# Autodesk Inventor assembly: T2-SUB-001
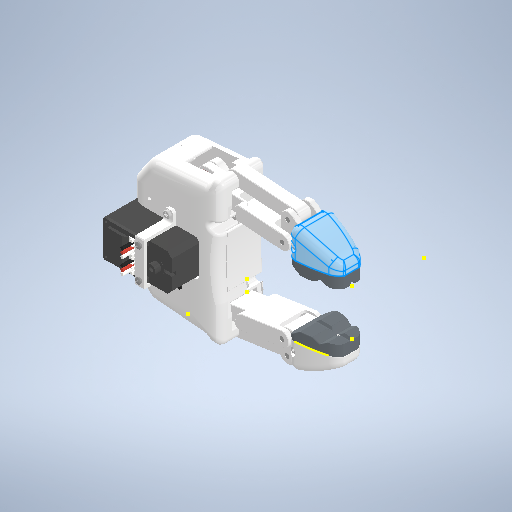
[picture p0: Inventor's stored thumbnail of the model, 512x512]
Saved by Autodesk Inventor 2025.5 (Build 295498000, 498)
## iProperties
Created: 2026-10
Part Number: T2-SUB-001
Document SubType Name: Assembly
Designer: Luis MuÃ±oz
Project: TESIS 2 - Plataforma mecatrÃ³nica preventiva desacoplada
Description: Gripper adaptativo instrumentado con puntas flexibles
Author: Luis M
Title: Gripper adaptativo instrumentado con puntas flexibles
Revision Number: 00
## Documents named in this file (22)
- C:\Users\Luis M\Desktop\TESIS\CAD_TESIS_ORGANIZADO\01_ENSAMBLES\GRIPPER_ADAPTATIVO_INSTRUMENTADO.iam
- C:\Users\Luis M\Desktop\TESIS\CAD_TESIS_ORGANIZADO\02_PIEZAS\GRIPPER\PLACA_INFERIOR_GRIPPER.ipt
- C:\Users\Luis M\Desktop\TESIS\CAD_TESIS_ORGANIZADO\02_PIEZAS\GRIPPER\ESLABON_INTERIOR.ipt
- C:\Users\Luis M\Desktop\TESIS\CAD_TESIS_ORGANIZADO\02_PIEZAS\GRIPPER\ESLABON_EXTERIOR.ipt
- C:\Users\Luis M\Desktop\TESIS\CAD_TESIS_ORGANIZADO\02_PIEZAS\GRIPPER\ESLABON_DISTAL.ipt
- C:\Users\Luis M\Desktop\TESIS\CAD_TESIS_ORGANIZADO\02_PIEZAS\GRIPPER\CARCASA_DISTAL_DEDO.ipt
- C:\Users\Luis M\Desktop\TESIS\CAD_TESIS_ORGANIZADO\02_PIEZAS\GRIPPER\SOPORTE_PUNTA_FLEXIBLE.ipt
- C:\Users\Luis M\Desktop\TESIS\CAD_TESIS_ORGANIZADO\02_PIEZAS\GRIPPER\PUNTA_CONTACTO_REMOVIBLE.ipt
- C:\Users\Luis M\Desktop\TESIS\CAD_TESIS_ORGANIZADO\02_PIEZAS\GRIPPER\PLACA_SUPERIOR_GRIPPER.ipt
- C:\Users\Luis M\Desktop\TESIS\CAD_TESIS_ORGANIZADO\02_PIEZAS\COMERCIALES_COMPARTIDAS\FEETECH_ST-3215-C018.iam
- C:\Users\Luis M\Desktop\TESIS\CAD_TESIS_ORGANIZADO\02_PIEZAS\GRIPPER\ACOPLE_EJE_SERVOMOTOR.ipt
- C:\Users\Luis M\Desktop\TESIS\CAD_TESIS_ORGANIZADO\02_PIEZAS\GRIPPER\LEVA_ACCIONAMIENTO.ipt
- C:\Users\Luis M\Desktop\TESIS\CAD_TESIS_ORGANIZADO\02_PIEZAS\GRIPPER\BIELA_MOTRIZ.ipt
- C:\Users\Luis M\Desktop\TESIS\CAD_TESIS_ORGANIZADO\02_PIEZAS\COMERCIALES_COMPARTIDAS\MCM_99461A931_TORNILLO_M2_5X8.ipt
- C:\Users\Luis M\Desktop\TESIS\CAD_TESIS_ORGANIZADO\02_PIEZAS\COMERCIALES_COMPARTIDAS\INSERTO_ROSCADO_M3_D5_L5.ipt
- C:\Users\Luis M\Desktop\TESIS\CAD_TESIS_ORGANIZADO\02_PIEZAS\COMERCIALES_COMPARTIDAS\PASADOR_CILINDRICO_D3X16.ipt
- C:\Users\Luis M\Desktop\TESIS\CAD_TESIS_ORGANIZADO\02_PIEZAS\COMERCIALES_COMPARTIDAS\PASADOR_CILINDRICO_D3X24.ipt
- C:\Users\Luis M\Desktop\TESIS\CAD_TESIS_ORGANIZADO\02_PIEZAS\COMERCIALES_COMPARTIDAS\COJINETE_LISO_D3_D6_L5.ipt
- C:\Users\Luis M\Desktop\TESIS\CAD_TESIS_ORGANIZADO\02_PIEZAS\COMERCIALES_COMPARTIDAS\TORNILLO_HEX_INTERIOR_M3X10.ipt
- C:\Users\Luis M\Desktop\TESIS\CAD_TESIS_ORGANIZADO\02_PIEZAS\GRIPPER\BRIDA_SERVOMOTOR.ipt
- C:\Users\Luis M\Desktop\TESIS\CAD_TESIS_ORGANIZADO\02_PIEZAS\COMERCIALES_COMPARTIDAS\TORNILLO_M2X4.ipt
- C:\Users\Luis M\Desktop\TESIS\CAD_TESIS_ORGANIZADO\02_PIEZAS\COMERCIALES_COMPARTIDAS\TORNILLO_HEX_INTERIOR_M3X6.ipt
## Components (70 placed, 21 different names)
1. PLACA_INFERIOR_GRIPPER:1
2. ESLABON_INTERIOR:1 — Coincidencia:1, Coincidencia:2, Coincidencia:12, Coincidencia:13, Coincidencia:49, Nivelación:13, Coincidencia:65, Coincidencia:66, Nivelación:15, Coincidencia:87, Coincidencia:92
3. ESLABON_INTERIOR:2 — Coincidencia:3, Coincidencia:4, Coincidencia:9, Coincidencia:14, Coincidencia:47, Nivelación:10, Coincidencia:63, Coincidencia:64, Nivelación:14, Coincidencia:89
4. ESLABON_EXTERIOR:1 — Coincidencia:6, Coincidencia:7, Coincidencia:11, Coincidencia:69
5. ESLABON_EXTERIOR:2 — Coincidencia:5, Coincidencia:8, Coincidencia:10, Coincidencia:70
6. ESLABON_DISTAL:1
7. ESLABON_DISTAL:2
8. Distal_Shell:2 — Coincidencia:15, Coincidencia:23, Nivelación:2, Nivelación:3, Coincidencia:71, Coincidencia:73, Coincidencia:74, Coincidencia:136
9. Distal_Shell:3 — Coincidencia:16, Coincidencia:24, Nivelación:1, Nivelación:4, Coincidencia:77, Coincidencia:78, Coincidencia:137
10. SOPORTE_PUNTA_FLEXIBLE:1 — Nivelación:3, Coincidencia:28, Coincidencia:136
11. SOPORTE_PUNTA_FLEXIBLE:2 — Coincidencia:29, Nivelación:4, Coincidencia:137
12. PUNTA_CONTACTO_REMOVIBLE:1 — Coincidencia:17, Coincidencia:18, Coincidencia:22, Coincidencia:23, Nivelación:2, Coincidencia:28, Coincidencia:57, Coincidencia:58, Coincidencia:59, Coincidencia:60, Coincidencia:61, Coincidencia:62, Coincidencia:72
13. PUNTA_CONTACTO_REMOVIBLE:2 — Coincidencia:19, Coincidencia:20, Coincidencia:21, Coincidencia:24, Nivelación:1, Coincidencia:29, Coincidencia:51, Coincidencia:52, Coincidencia:53, Coincidencia:54, Coincidencia:55, Coincidencia:56, Coincidencia:75, Coincidencia:76
14. PLACA_SUPERIOR_GRIPPER:1 — Coincidencia:25, Coincidencia:26, Coincidencia:27, Coincidencia:30, Coincidencia:31, Nivelación:5, Coincidencia:98, Coincidencia:99, Coincidencia:100, Coincidencia:102, Coincidencia:103, Coincidencia:104, Coincidencia:105, Coincidencia:106, Coincidencia:122, Coincidencia:123, Coincidencia:124, Coincidencia:126, Coincidencia:127, Coincidencia:130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
15. FEETECH_ST-3215-C018:1 [sub-assembly] — Coincidencia:30, Coincidencia:31, Nivelación:5, Coincidencia:35, Coincidencia:36, Coincidencia:135
16. ACOPLE_EJE:2 — Coincidencia:32, Coincidencia:33, Coincidencia:34, Coincidencia:36
17. Cam:1 — Coincidencia:32, Coincidencia:33, Coincidencia:34, Coincidencia:35, Coincidencia:45, Coincidencia:46, Nivelación:8, Nivelación:9, Coincidencia:112, Coincidencia:113, Coincidencia:114, Coincidencia:115, Coincidencia:116, Coincidencia:117, Coincidencia:118, Coincidencia:119, Coincidencia:120, Coincidencia:121, Coincidencia:135
18. BIELA_MOTRIZ:1 — Coincidencia:79, Coincidencia:80, Coincidencia:84, Nivelación:19, Coincidencia:85, Nivelación:21, Coincidencia:87
19. BIELA_MOTRIZ:2 — Coincidencia:81, Coincidencia:82, Coincidencia:83, Nivelación:18, Nivelación:20, Coincidencia:88, Coincidencia:89
20. MCM_99461A931_TORNILLO_M2_5X8:1 — Coincidencia:57, Coincidencia:61
21. INSERTO_ROSCADO_M3_D5_L5:1 — Coincidencia:85, Nivelación:21
22. PASADOR_CILINDRICO_D3X16:1 — Coincidencia:68, Nivelación:17
23. PASADOR_CILINDRICO_D3X24:1 — Coincidencia:65
24. COJINETE_LISO_D3_D6_L5:1 — Coincidencia:49, Nivelación:13, Coincidencia:79, Coincidencia:91
25. MCM_99461A931_TORNILLO_M2_5X8:2 — Coincidencia:101, Coincidencia:107
26. INSERTO_ROSCADO_M3_D5_L5:2 — Nivelación:20, Coincidencia:88
27. PASADOR_CILINDRICO_D3X16:2 — Coincidencia:69
28. PASADOR_CILINDRICO_D3X24:2 — Coincidencia:66, Nivelación:15
29. COJINETE_LISO_D3_D6_L5:2 — Coincidencia:83, Nivelación:18, Coincidencia:95, Coincidencia:96
30. MCM_99461A931_TORNILLO_M2_5X8:3 — Coincidencia:71, Coincidencia:73
31. INSERTO_ROSCADO_M3_D5_L5:3 — Coincidencia:45, Nivelación:9, Coincidencia:80
32. PASADOR_CILINDRICO_D3X16:3 — Coincidencia:67, Nivelación:16
33. PASADOR_CILINDRICO_D3X24:3 — Coincidencia:63
34. COJINETE_LISO_D3_D6_L5:3 — Coincidencia:47, Nivelación:10, Coincidencia:82, Coincidencia:90, Coincidencia:93
35. MCM_99461A931_TORNILLO_M2_5X8:4 — Coincidencia:72, Coincidencia:74
36. INSERTO_ROSCADO_M3_D5_L5:4 — Coincidencia:46, Nivelación:8, Coincidencia:81
37. PASADOR_CILINDRICO_D3X16:4 — Coincidencia:70
38. PASADOR_CILINDRICO_D3X24:4 — Coincidencia:64, Nivelación:14
39. COJINETE_LISO_D3_D6_L5:4 — Coincidencia:84, Nivelación:19, Coincidencia:94, Coincidencia:97
40. MCM_99461A931_TORNILLO_M2_5X8:5 — Coincidencia:102, Coincidencia:108
41. MCM_99461A931_TORNILLO_M2_5X8:6 — Coincidencia:104, Coincidencia:105
42. MCM_99461A931_TORNILLO_M2_5X8:7 — Coincidencia:75, Coincidencia:77
43. MCM_99461A931_TORNILLO_M2_5X8:8 — Coincidencia:76, Coincidencia:78
44. MCM_99461A931_TORNILLO_M2_5X8:10 — Coincidencia:125, Coincidencia:129
45. MCM_99461A931_TORNILLO_M2_5X8:11 — Coincidencia:122, Coincidencia:127
46. MCM_99461A931_TORNILLO_M2_5X8:12 — Coincidencia:123, Coincidencia:126
47. MCM_99461A931_TORNILLO_M2_5X8:13 — Coincidencia:51, Coincidencia:56
48. MCM_99461A931_TORNILLO_M2_5X8:14 — Coincidencia:58, Coincidencia:62
49. MCM_99461A931_TORNILLO_M2_5X8:16 — Coincidencia:124, Coincidencia:128
50. MCM_99461A931_TORNILLO_M2_5X8:17 — Coincidencia:52, Coincidencia:54
51. MCM_99461A931_TORNILLO_M2_5X8:18 — Coincidencia:53, Coincidencia:55
52. MCM_99461A931_TORNILLO_M2_5X8:19 — Coincidencia:59, Coincidencia:60
53. MCM_99461A931_TORNILLO_M2_5X8:20 — Coincidencia:103, Coincidencia:106
54. hex_socket_cylindrical_head_M3x10:1 — Coincidencia:90, Coincidencia:93
55. hex_socket_cylindrical_head_M3x10:2 — Coincidencia:91, Coincidencia:92
56. hex_socket_cylindrical_head_M3x10:3 — Coincidencia:94, Coincidencia:97
57. hex_socket_cylindrical_head_M3x10:4 — Coincidencia:95, Coincidencia:96
58. BRIDA_SERVOMOTOR:1
59. TORNILLO_M2X4:1 — Coincidencia:109, Nivelación:22
60. TORNILLO_M2X4:2 — Coincidencia:110, Nivelación:22, Coincidencia:111
61. TORNILLO_HEX_INTERIOR_M3X6:1 — Coincidencia:114, Coincidencia:120
62. TORNILLO_HEX_INTERIOR_M3X6:2 — Coincidencia:112, Coincidencia:113
63. TORNILLO_HEX_INTERIOR_M3X6:3 — Coincidencia:116, Coincidencia:119
64. TORNILLO_HEX_INTERIOR_M3X6:4 — Coincidencia:117, Coincidencia:118
65. TORNILLO_HEX_INTERIOR_M3X6:5 — Coincidencia:115, Coincidencia:121
66. INSERTO_ROSCADO_M3_D5_L5:9 — Coincidencia:131, Nivelación:27
67. INSERTO_ROSCADO_M3_D5_L5:10 — Coincidencia:130, Nivelación:23
68. INSERTO_ROSCADO_M3_D5_L5:11 — Coincidencia:134, Nivelación:26
69. INSERTO_ROSCADO_M3_D5_L5:12 — Coincidencia:132, Nivelación:24
70. INSERTO_ROSCADO_M3_D5_L5:13 — Coincidencia:133, Nivelación:25
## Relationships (149: Mate 126, Flush 23)
- Coincidencia:1 [Mate]: ESLABON_INTERIOR:1
- Coincidencia:2 [Mate]: ESLABON_INTERIOR:1
- Coincidencia:3 [Mate]: ESLABON_INTERIOR:2
- Coincidencia:4 [Mate]: ESLABON_INTERIOR:2
- Coincidencia:5 [Mate]: ESLABON_EXTERIOR:2
- Coincidencia:6 [Mate]: ESLABON_EXTERIOR:1
- Coincidencia:7 [Mate]: ESLABON_EXTERIOR:1
- Coincidencia:8 [Mate]: ESLABON_EXTERIOR:2
- Coincidencia:9 [Mate]: ESLABON_INTERIOR:2
- Coincidencia:10 [Mate]: ESLABON_EXTERIOR:2
- Coincidencia:11 [Mate]: ESLABON_EXTERIOR:1
- Coincidencia:12 [Mate]: ESLABON_INTERIOR:1
- Coincidencia:13 [Mate]: ESLABON_INTERIOR:1
- Coincidencia:14 [Mate]: ESLABON_INTERIOR:2
- Coincidencia:15 [Mate]: Distal_Shell:2
- Coincidencia:16 [Mate]: Distal_Shell:3
- Coincidencia:17 [Mate]: PUNTA_CONTACTO_REMOVIBLE:1
- Coincidencia:18 [Mate]: PUNTA_CONTACTO_REMOVIBLE:1
- Coincidencia:19 [Mate]: PUNTA_CONTACTO_REMOVIBLE:2
- Coincidencia:20 [Mate]: PUNTA_CONTACTO_REMOVIBLE:2
- Coincidencia:21 [Mate]: PUNTA_CONTACTO_REMOVIBLE:2
- Coincidencia:22 [Mate]: PUNTA_CONTACTO_REMOVIBLE:1
- Coincidencia:23 [Mate]: Distal_Shell:2 ↔ PUNTA_CONTACTO_REMOVIBLE:1
- Coincidencia:24 [Mate]: Distal_Shell:3 ↔ PUNTA_CONTACTO_REMOVIBLE:2
- Nivelación:1 [Flush]: Distal_Shell:3 ↔ PUNTA_CONTACTO_REMOVIBLE:2
- Nivelación:2 [Flush]: Distal_Shell:2 ↔ PUNTA_CONTACTO_REMOVIBLE:1
- Coincidencia:25 [Mate]: PLACA_SUPERIOR_GRIPPER:1
- Coincidencia:26 [Mate]: PLACA_SUPERIOR_GRIPPER:1
- Coincidencia:27 [Mate]: PLACA_SUPERIOR_GRIPPER:1
- Nivelación:3 [Flush]: Distal_Shell:2 ↔ SOPORTE_PUNTA_FLEXIBLE:1
- Coincidencia:28 [Mate]: SOPORTE_PUNTA_FLEXIBLE:1 ↔ PUNTA_CONTACTO_REMOVIBLE:1
- Coincidencia:29 [Mate]: SOPORTE_PUNTA_FLEXIBLE:2 ↔ PUNTA_CONTACTO_REMOVIBLE:2
- Nivelación:4 [Flush]: Distal_Shell:3 ↔ SOPORTE_PUNTA_FLEXIBLE:2
- Coincidencia:30 [Mate]: PLACA_SUPERIOR_GRIPPER:1 ↔ FEETECH_ST-3215-C018:1
- Coincidencia:31 [Mate]: PLACA_SUPERIOR_GRIPPER:1 ↔ FEETECH_ST-3215-C018:1
- Nivelación:5 [Flush]: PLACA_SUPERIOR_GRIPPER:1 ↔ FEETECH_ST-3215-C018:1
- Coincidencia:32 [Mate]: ACOPLE_EJE:2 ↔ Cam:1
- Coincidencia:33 [Mate]: ACOPLE_EJE:2 ↔ Cam:1
- Coincidencia:34 [Mate]: ACOPLE_EJE:2 ↔ Cam:1
- Coincidencia:35 [Mate]: FEETECH_ST-3215-C018:1 ↔ Cam:1
- Coincidencia:36 [Mate]: FEETECH_ST-3215-C018:1 ↔ ACOPLE_EJE:2
- Coincidencia:45 [Mate]: Cam:1 ↔ INSERTO_ROSCADO_M3_D5_L5:3
- Coincidencia:46 [Mate]: Cam:1 ↔ INSERTO_ROSCADO_M3_D5_L5:4
- Nivelación:8 [Flush]: Cam:1 ↔ INSERTO_ROSCADO_M3_D5_L5:4
- Nivelación:9 [Flush]: Cam:1 ↔ INSERTO_ROSCADO_M3_D5_L5:3
- Coincidencia:47 [Mate]: ESLABON_INTERIOR:2 ↔ COJINETE_LISO_D3_D6_L5:3
- Coincidencia:49 [Mate]: ESLABON_INTERIOR:1 ↔ COJINETE_LISO_D3_D6_L5:1
- Nivelación:10 [Flush]: ESLABON_INTERIOR:2 ↔ COJINETE_LISO_D3_D6_L5:3
- Nivelación:13 [Flush]: ESLABON_INTERIOR:1 ↔ COJINETE_LISO_D3_D6_L5:1
- Coincidencia:51 [Mate]: PUNTA_CONTACTO_REMOVIBLE:2 ↔ MCM_99461A931_TORNILLO_M2_5X8:13
- Coincidencia:52 [Mate]: PUNTA_CONTACTO_REMOVIBLE:2 ↔ MCM_99461A931_TORNILLO_M2_5X8:17
- Coincidencia:53 [Mate]: PUNTA_CONTACTO_REMOVIBLE:2 ↔ MCM_99461A931_TORNILLO_M2_5X8:18
- Coincidencia:54 [Mate]: PUNTA_CONTACTO_REMOVIBLE:2 ↔ MCM_99461A931_TORNILLO_M2_5X8:17
- Coincidencia:55 [Mate]: PUNTA_CONTACTO_REMOVIBLE:2 ↔ MCM_99461A931_TORNILLO_M2_5X8:18
- Coincidencia:56 [Mate]: PUNTA_CONTACTO_REMOVIBLE:2 ↔ MCM_99461A931_TORNILLO_M2_5X8:13
- Coincidencia:57 [Mate]: PUNTA_CONTACTO_REMOVIBLE:1 ↔ MCM_99461A931_TORNILLO_M2_5X8:1
- Coincidencia:58 [Mate]: PUNTA_CONTACTO_REMOVIBLE:1 ↔ MCM_99461A931_TORNILLO_M2_5X8:14
- Coincidencia:59 [Mate]: PUNTA_CONTACTO_REMOVIBLE:1 ↔ MCM_99461A931_TORNILLO_M2_5X8:19
- Coincidencia:60 [Mate]: PUNTA_CONTACTO_REMOVIBLE:1 ↔ MCM_99461A931_TORNILLO_M2_5X8:19
- Coincidencia:61 [Mate]: PUNTA_CONTACTO_REMOVIBLE:1 ↔ MCM_99461A931_TORNILLO_M2_5X8:1
- Coincidencia:62 [Mate]: PUNTA_CONTACTO_REMOVIBLE:1 ↔ MCM_99461A931_TORNILLO_M2_5X8:14
- Coincidencia:63 [Mate]: ESLABON_INTERIOR:2 ↔ PASADOR_CILINDRICO_D3X24:3
- Coincidencia:64 [Mate]: ESLABON_INTERIOR:2 ↔ PASADOR_CILINDRICO_D3X24:4
- Coincidencia:65 [Mate]: ESLABON_INTERIOR:1 ↔ PASADOR_CILINDRICO_D3X24:1
- Coincidencia:66 [Mate]: ESLABON_INTERIOR:1 ↔ PASADOR_CILINDRICO_D3X24:2
- Nivelación:14 [Flush]: ESLABON_INTERIOR:2 ↔ PASADOR_CILINDRICO_D3X24:4
- Nivelación:15 [Flush]: ESLABON_INTERIOR:1 ↔ PASADOR_CILINDRICO_D3X24:2
- Coincidencia:67 [Mate]: PASADOR_CILINDRICO_D3X16:3
- Coincidencia:68 [Mate]: PASADOR_CILINDRICO_D3X16:1
- Coincidencia:69 [Mate]: ESLABON_EXTERIOR:1 ↔ PASADOR_CILINDRICO_D3X16:2
- Coincidencia:70 [Mate]: ESLABON_EXTERIOR:2 ↔ PASADOR_CILINDRICO_D3X16:4
- Nivelación:16 [Flush]: PASADOR_CILINDRICO_D3X16:3
- Nivelación:17 [Flush]: PASADOR_CILINDRICO_D3X16:1
- Coincidencia:71 [Mate]: Distal_Shell:2 ↔ MCM_99461A931_TORNILLO_M2_5X8:3
- Coincidencia:72 [Mate]: PUNTA_CONTACTO_REMOVIBLE:1 ↔ MCM_99461A931_TORNILLO_M2_5X8:4
- Coincidencia:73 [Mate]: Distal_Shell:2 ↔ MCM_99461A931_TORNILLO_M2_5X8:3
- Coincidencia:74 [Mate]: Distal_Shell:2 ↔ MCM_99461A931_TORNILLO_M2_5X8:4
- Coincidencia:75 [Mate]: PUNTA_CONTACTO_REMOVIBLE:2 ↔ MCM_99461A931_TORNILLO_M2_5X8:7
- Coincidencia:76 [Mate]: PUNTA_CONTACTO_REMOVIBLE:2 ↔ MCM_99461A931_TORNILLO_M2_5X8:8
- Coincidencia:77 [Mate]: Distal_Shell:3 ↔ MCM_99461A931_TORNILLO_M2_5X8:7
- Coincidencia:78 [Mate]: Distal_Shell:3 ↔ MCM_99461A931_TORNILLO_M2_5X8:8
- Coincidencia:79 [Mate]: BIELA_MOTRIZ:1 ↔ COJINETE_LISO_D3_D6_L5:1
- Coincidencia:80 [Mate]: BIELA_MOTRIZ:1 ↔ INSERTO_ROSCADO_M3_D5_L5:3
- Coincidencia:81 [Mate]: BIELA_MOTRIZ:2 ↔ INSERTO_ROSCADO_M3_D5_L5:4
- Coincidencia:82 [Mate]: BIELA_MOTRIZ:2 ↔ COJINETE_LISO_D3_D6_L5:3
- Coincidencia:83 [Mate]: BIELA_MOTRIZ:2 ↔ COJINETE_LISO_D3_D6_L5:2
- Nivelación:18 [Flush]: BIELA_MOTRIZ:2 ↔ COJINETE_LISO_D3_D6_L5:2
- Coincidencia:84 [Mate]: BIELA_MOTRIZ:1 ↔ COJINETE_LISO_D3_D6_L5:4
- Nivelación:19 [Flush]: BIELA_MOTRIZ:1 ↔ COJINETE_LISO_D3_D6_L5:4
- Coincidencia:85 [Mate]: BIELA_MOTRIZ:1 ↔ INSERTO_ROSCADO_M3_D5_L5:1
- Nivelación:20 [Flush]: BIELA_MOTRIZ:2 ↔ INSERTO_ROSCADO_M3_D5_L5:2
- Nivelación:21 [Flush]: BIELA_MOTRIZ:1 ↔ INSERTO_ROSCADO_M3_D5_L5:1
- Coincidencia:87 [Mate]: ESLABON_INTERIOR:1 ↔ BIELA_MOTRIZ:1
- Coincidencia:88 [Mate]: BIELA_MOTRIZ:2 ↔ INSERTO_ROSCADO_M3_D5_L5:2
- Coincidencia:89 [Mate]: ESLABON_INTERIOR:2 ↔ BIELA_MOTRIZ:2
- Coincidencia:90 [Mate]: COJINETE_LISO_D3_D6_L5:3 ↔ hex_socket_cylindrical_head_M3x10:1
- Coincidencia:91 [Mate]: COJINETE_LISO_D3_D6_L5:1 ↔ hex_socket_cylindrical_head_M3x10:2
- Coincidencia:92 [Mate]: ESLABON_INTERIOR:1 ↔ hex_socket_cylindrical_head_M3x10:2
- Coincidencia:93 [Mate]: COJINETE_LISO_D3_D6_L5:3 ↔ hex_socket_cylindrical_head_M3x10:1
- Coincidencia:94 [Mate]: COJINETE_LISO_D3_D6_L5:4 ↔ hex_socket_cylindrical_head_M3x10:3
- Coincidencia:95 [Mate]: COJINETE_LISO_D3_D6_L5:2 ↔ hex_socket_cylindrical_head_M3x10:4
- Coincidencia:96 [Mate]: COJINETE_LISO_D3_D6_L5:2 ↔ hex_socket_cylindrical_head_M3x10:4
- Coincidencia:97 [Mate]: COJINETE_LISO_D3_D6_L5:4 ↔ hex_socket_cylindrical_head_M3x10:3
- Coincidencia:98 [Mate]: PLACA_SUPERIOR_GRIPPER:1
- Coincidencia:99 [Mate]: PLACA_SUPERIOR_GRIPPER:1
- Coincidencia:100 [Mate]: PLACA_SUPERIOR_GRIPPER:1
- Coincidencia:101 [Mate]: MCM_99461A931_TORNILLO_M2_5X8:2
- Coincidencia:102 [Mate]: PLACA_SUPERIOR_GRIPPER:1 ↔ MCM_99461A931_TORNILLO_M2_5X8:5
- Coincidencia:103 [Mate]: PLACA_SUPERIOR_GRIPPER:1 ↔ MCM_99461A931_TORNILLO_M2_5X8:20
- Coincidencia:104 [Mate]: PLACA_SUPERIOR_GRIPPER:1 ↔ MCM_99461A931_TORNILLO_M2_5X8:6
- Coincidencia:105 [Mate]: PLACA_SUPERIOR_GRIPPER:1 ↔ MCM_99461A931_TORNILLO_M2_5X8:6
- Coincidencia:106 [Mate]: PLACA_SUPERIOR_GRIPPER:1 ↔ MCM_99461A931_TORNILLO_M2_5X8:20
- Coincidencia:107 [Mate]: MCM_99461A931_TORNILLO_M2_5X8:2
- Coincidencia:108 [Mate]: MCM_99461A931_TORNILLO_M2_5X8:5
- Coincidencia:109 [Mate]: TORNILLO_M2X4:1
- Coincidencia:110 [Mate]: TORNILLO_M2X4:2
- Nivelación:22 [Flush]: TORNILLO_M2X4:1 ↔ TORNILLO_M2X4:2
- Coincidencia:111 [Mate]: TORNILLO_M2X4:2
- Coincidencia:112 [Mate]: Cam:1 ↔ TORNILLO_HEX_INTERIOR_M3X6:2
- Coincidencia:113 [Mate]: Cam:1 ↔ TORNILLO_HEX_INTERIOR_M3X6:2
- Coincidencia:114 [Mate]: Cam:1 ↔ TORNILLO_HEX_INTERIOR_M3X6:1
- Coincidencia:115 [Mate]: Cam:1 ↔ TORNILLO_HEX_INTERIOR_M3X6:5
- Coincidencia:116 [Mate]: Cam:1 ↔ TORNILLO_HEX_INTERIOR_M3X6:3
- Coincidencia:117 [Mate]: Cam:1 ↔ TORNILLO_HEX_INTERIOR_M3X6:4
- Coincidencia:118 [Mate]: Cam:1 ↔ TORNILLO_HEX_INTERIOR_M3X6:4
- Coincidencia:119 [Mate]: Cam:1 ↔ TORNILLO_HEX_INTERIOR_M3X6:3
- Coincidencia:120 [Mate]: Cam:1 ↔ TORNILLO_HEX_INTERIOR_M3X6:1
- Coincidencia:121 [Mate]: Cam:1 ↔ TORNILLO_HEX_INTERIOR_M3X6:5
- Coincidencia:122 [Mate]: PLACA_SUPERIOR_GRIPPER:1 ↔ MCM_99461A931_TORNILLO_M2_5X8:11
- Coincidencia:123 [Mate]: PLACA_SUPERIOR_GRIPPER:1 ↔ MCM_99461A931_TORNILLO_M2_5X8:12
- Coincidencia:124 [Mate]: PLACA_SUPERIOR_GRIPPER:1 ↔ MCM_99461A931_TORNILLO_M2_5X8:16
- Coincidencia:125 [Mate]: MCM_99461A931_TORNILLO_M2_5X8:10
- Coincidencia:126 [Mate]: PLACA_SUPERIOR_GRIPPER:1 ↔ MCM_99461A931_TORNILLO_M2_5X8:12
- Coincidencia:127 [Mate]: PLACA_SUPERIOR_GRIPPER:1 ↔ MCM_99461A931_TORNILLO_M2_5X8:11
- Coincidencia:128 [Mate]: MCM_99461A931_TORNILLO_M2_5X8:16
- Coincidencia:129 [Mate]: MCM_99461A931_TORNILLO_M2_5X8:10
- Coincidencia:130 [Mate]: PLACA_SUPERIOR_GRIPPER:1 ↔ INSERTO_ROSCADO_M3_D5_L5:10
- Coincidencia:131 [Mate]: PLACA_SUPERIOR_GRIPPER:1 ↔ INSERTO_ROSCADO_M3_D5_L5:9
- Coincidencia:132 [Mate]: INSERTO_ROSCADO_M3_D5_L5:12
- Coincidencia:133 [Mate]: INSERTO_ROSCADO_M3_D5_L5:13
- Coincidencia:134 [Mate]: INSERTO_ROSCADO_M3_D5_L5:11
- Nivelación:23 [Flush]: PLACA_SUPERIOR_GRIPPER:1 ↔ INSERTO_ROSCADO_M3_D5_L5:10
- Nivelación:24 [Flush]: INSERTO_ROSCADO_M3_D5_L5:12
- Nivelación:25 [Flush]: INSERTO_ROSCADO_M3_D5_L5:13
- Nivelación:26 [Flush]: INSERTO_ROSCADO_M3_D5_L5:11
- Nivelación:27 [Flush]: PLACA_SUPERIOR_GRIPPER:1 ↔ INSERTO_ROSCADO_M3_D5_L5:9
- Coincidencia:135 [Mate]: FEETECH_ST-3215-C018:1 ↔ Cam:1
- Coincidencia:136 [Mate]: Distal_Shell:2 ↔ SOPORTE_PUNTA_FLEXIBLE:1
- Coincidencia:137 [Mate]: Distal_Shell:3 ↔ SOPORTE_PUNTA_FLEXIBLE:2
